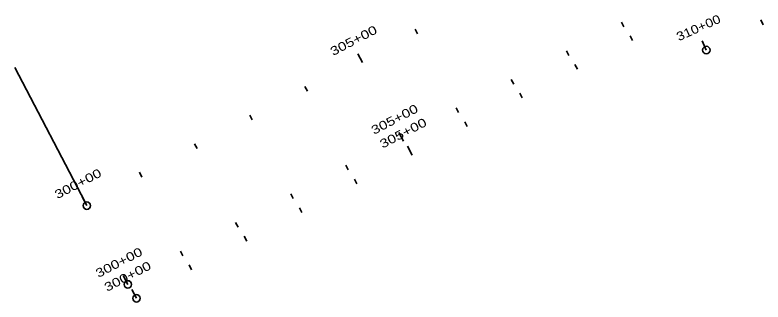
# Model space of a CAD drawing. Extents: x 2357892 to 2370172, y 6966790 to 6985499.
# Drawn here: x 2357892 to 2359096, y 6975764 to 6976227 of the extents above; entities that cross this region are included whole.
import ezdxf
from ezdxf.enums import TextEntityAlignment as Align

# ---------------------------------------------------------------- set-up
doc = ezdxf.new("R2010")
doc.units = 0
doc.header["$LTSCALE"] = 5.6
doc.layers.add('28', color=7, linetype='Continuous', lineweight=35)

msp = doc.modelspace()

# ---------------------------------------------------------------- linework, layer by layer
at = {"layer": '28'}
for p, q in [((2358871.82, 6976207.655), (2358867.901, 6976215.198)), ((2359095.72, 6976210.905), (2359092.255, 6976218.667)), ((2358539.665, 6976196.226), (2358535.745, 6976203.769)), ((2358885.566, 6976185.655), (2358881.642, 6976193.195)), ((2359004.406, 6976170.14), (2358997.884, 6976184.75)), ((2358450.935, 6976150.108), (2358443.556, 6976164.305)), ((2358783.088, 6976161.541), (2358779.168, 6976169.083)), ((2358004.516, 6975924.839), (2357891.58, 6976142.124)), ((2358796.858, 6976139.493), (2358792.934, 6976147.034)), ((2358694.355, 6976115.427), (2358690.435, 6976122.969)), ((2358362.204, 6976103.989), (2358358.284, 6976111.531)), ((2358708.15, 6976093.332), (2358704.226, 6976100.872)), ((2358605.623, 6976069.313), (2358601.703, 6976076.855)), ((2358273.474, 6976057.871), (2358269.554, 6976065.413)), ((2358619.441, 6976047.171), (2358615.518, 6976054.711)), ((2358516.89, 6976023.198), (2358509.512, 6976037.396)), ((2358184.744, 6976011.752), (2358180.824, 6976019.294)), ((2358530.733, 6976001.009), (2358523.348, 6976015.202)), ((2358428.157, 6975977.084), (2358424.238, 6975984.626)), ((2358096.013, 6975965.634), (2358092.093, 6975973.176)), ((2358442.025, 6975954.848), (2358438.102, 6975962.388)), ((2358007.283, 6975919.515), (2357999.904, 6975933.712)), ((2358339.425, 6975930.97), (2358335.505, 6975938.512)), ((2358353.317, 6975908.686), (2358349.394, 6975916.226)), ((2358250.692, 6975884.856), (2358246.772, 6975892.398)), ((2358264.609, 6975862.525), (2358260.685, 6975870.065)), ((2358161.96, 6975838.741), (2358158.04, 6975846.284)), ((2358175.901, 6975816.363), (2358171.977, 6975823.904)), ((2358073.227, 6975792.627), (2358065.849, 6975806.824)), ((2358087.193, 6975770.202), (2358079.807, 6975784.395))]:
    msp.add_line(p, q, dxfattribs=at)
for centre in [(2359004.406, 6976170.14), (2358007.283, 6975919.515), (2358073.227, 6975792.627), (2358087.193, 6975770.202)]:
    msp.add_circle(centre, 6, dxfattribs=at)

# ---------------------------------------------------------------- texts
for s, rotation, width, p in [('310+00', 24.057, 1.2, (2358994.623, 6976199.722)), ('305+00', 27.464, 1.3, (2358439.867, 6976179.293)), ('305+00', 27.461, 1.3, (2358505.823, 6976052.383)), ('305+00', 27.491, 1.3, (2358519.656, 6976030.191)), ('300+00', 27.464, 1.3, (2357996.215, 6975948.699)), ('300+00', 27.461, 1.3, (2358062.159, 6975821.812)), ('300+00', 27.491, 1.3, (2358076.114, 6975799.383))]:
    msp.add_text(s, height=14, rotation=rotation, dxfattribs=dict(at, width=width)).set_placement(p, align=Align.CENTER)

doc.saveas('drawing.dxf')
